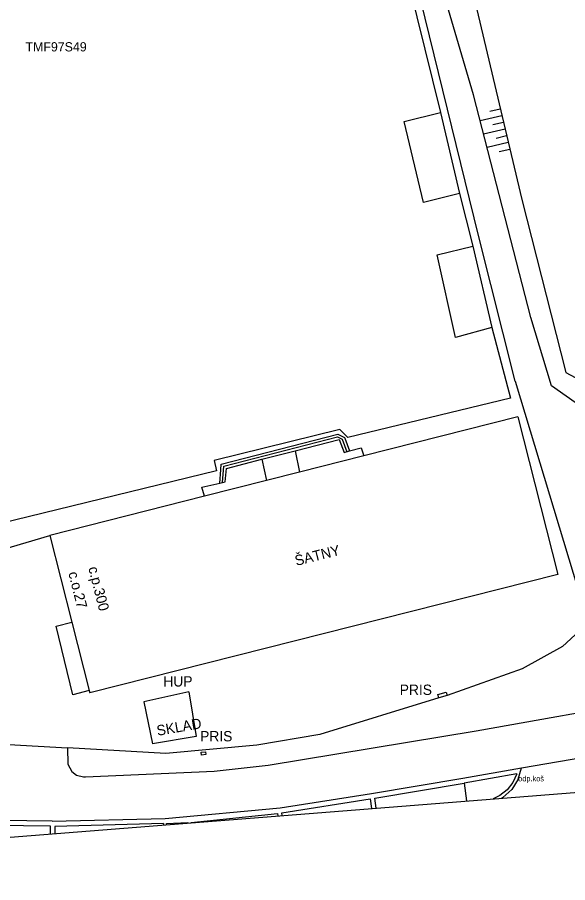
# Model space of a CAD drawing. Extents: x -597791 to -597535, y -1159670 to -1159547.
# Drawn here: x -597726 to -597686, y -1159669.5 to -1159606.7 of the extents above; entities that cross this region are included whole.
import ezdxf

# ---------------------------------------------------------------- set-up
doc = ezdxf.new("R2010")
doc.units = 0
doc.layers.add('MAPA', color=7, linetype='Continuous')
doc.layers.add('Žádosti', color=7, linetype='Continuous')

msp = doc.modelspace()

# ---------------------------------------------------------------- linework, layer by layer
at = {"layer": 'MAPA'}
for p, q in [((-597693.57, -1159662.31), (-597693.402, -1159663.602)), ((-597700.39, -1159663.44), (-597700.291, -1159664.147)), ((-597699.952, -1159664.12), (-597700.04, -1159663.4)), ((-597707.12, -1159664.51), (-597707.098, -1159664.685)), ((-597706.784, -1159664.66), (-597706.81, -1159664.46)), ((-597715.38, -1159665.25), (-597715.377, -1159665.34)), ((-597723.596, -1159665.989), (-597723.6, -1159665.43)), ((-597723.27, -1159665.45), (-597723.28, -1159665.964))]:
    msp.add_line(p, q, dxfattribs=at)
for points in [[(-597714.535, -1159550.725), (-597713.521, -1159552.063), (-597712.34, -1159553.62), (-597701.97, -1159569.58), (-597698.45, -1159581.43), (-597695.48, -1159594.37), (-597692.77, -1159605.67), (-597689.38, -1159619.96), (-597686.19, -1159632.52), (-597681.76, -1159634.88), (-597680.28, -1159632.32), (-597675.87, -1159632.46)], [(-597689.86, -1159633.14), (-597692.53, -1159622.57), (-597699.3, -1159594.96), (-597705.52, -1159569.32)], [(-597698.13, -1159602.09), (-597695.28, -1159613.64)], [(-597688.72, -1159628.53), (-597692.88, -1159612.36), (-597694.69, -1159606.19)], [(-597693.89, -1159619.52), (-597696.52, -1159620.18), (-597697.91, -1159614.3), (-597695.28, -1159613.64)], [(-597695.28, -1159613.64), (-597693.89, -1159619.52)], [(-597692.4, -1159614.24), (-597690.82, -1159613.86)], [(-597691.7, -1159613.56), (-597690.94, -1159613.38)], [(-597691.47, -1159614.53), (-597690.71, -1159614.35)], [(-597692.15, -1159615.2), (-597690.59, -1159614.84)], [(-597691.24, -1159615.5), (-597690.48, -1159615.32)], [(-597691.9, -1159616.17), (-597690.36, -1159615.81)], [(-597691.01, -1159616.48), (-597690.25, -1159616.3)], [(-597693.89, -1159619.52), (-597692.94, -1159623.34)], [(-597691.55, -1159629.25), (-597694.19, -1159629.97), (-597695.52, -1159623.97), (-597692.94, -1159623.34)], [(-597692.94, -1159623.34), (-597691.55, -1159629.25)], [(-597687.23, -1159633.48), (-597688.72, -1159628.53)], [(-597691.55, -1159629.25), (-597690.2, -1159634.37)], [(-597690.2, -1159634.37), (-597702, -1159637.24), (-597702.58, -1159636.66), (-597711.7, -1159638.91), (-597711.53, -1159639.64), (-597724.12, -1159642.71), (-597737.44, -1159645.96), (-597740.78, -1159632.5), (-597753.96, -1159635.73), (-597758.88, -1159636.94)], [(-597675.87, -1159632.46), (-597679.29, -1159633.21), (-597680.19, -1159635.65), (-597682.97, -1159636.48), (-597687.23, -1159633.48)], [(-597689.86, -1159633.14), (-597684.56, -1159650.67)], [(-597689.66, -1159635.74), (-597700.85, -1159638.57)], [(-597689.66, -1159635.74), (-597686.76, -1159647.16)], [(-597711.31, -1159640.54), (-597711.233, -1159639.569), (-597711.2, -1159639.16), (-597702.74, -1159636.98), (-597702.26, -1159637.22), (-597702.234, -1159637.288), (-597701.88, -1159638.21)], [(-597711.1, -1159640.49), (-597711.01, -1159639.31), (-597702.76, -1159637.19), (-597702.42, -1159637.36), (-597702.07, -1159638.26)], [(-597705.82, -1159638.19), (-597702.64, -1159637.37), (-597702.27, -1159638.31), (-597701.88, -1159638.21)], [(-597708.24, -1159638.81), (-597705.82, -1159638.19)], [(-597705.82, -1159638.19), (-597705.51, -1159639.75)], [(-597701.88, -1159638.21), (-597701.03, -1159637.99), (-597700.85, -1159638.57)], [(-597711.31, -1159640.54), (-597710.9, -1159640.45), (-597710.82, -1159639.47), (-597708.24, -1159638.81)], [(-597708.24, -1159638.81), (-597707.9, -1159640.35)], [(-597700.85, -1159638.57), (-597705.51, -1159639.75)], [(-597705.51, -1159639.75), (-597707.9, -1159640.35)], [(-597712.41, -1159641.49), (-597712.6, -1159640.84), (-597711.31, -1159640.54)], [(-597707.9, -1159640.35), (-597712.41, -1159641.49)], [(-597712.41, -1159641.49), (-597723.64, -1159644.34)], [(-597726.62, -1159659.5), (-597727.5, -1159658.36), (-597731.47, -1159657.68), (-597731.64, -1159654.22), (-597727, -1159653.26), (-597728.16, -1159645.66), (-597723.64, -1159644.34)], [(-597723.64, -1159644.34), (-597722.05, -1159650.62)], [(-597686.76, -1159647.16), (-597720.74, -1159655.77)], [(-597720.79, -1159655.6), (-597721.98, -1159655.9), (-597723.18, -1159650.91), (-597722.05, -1159650.62)], [(-597722.05, -1159650.62), (-597720.79, -1159655.6)], [(-597684.56, -1159650.67), (-597686.43, -1159652.4), (-597689.36, -1159654.01), (-597694.8, -1159655.94), (-597695.4, -1159656.12), (-597704.03, -1159658.79), (-597708.62, -1159659.55)], [(-597720.79, -1159655.6), (-597720.74, -1159655.77)], [(-597713.56, -1159655.68), (-597716.82, -1159656.4)], [(-597713.56, -1159655.68), (-597713.01, -1159658.92)], [(-597695.4, -1159656.12), (-597695.47, -1159655.89), (-597694.88, -1159655.7), (-597694.8, -1159655.94)], [(-597722.35, -1159659.75), (-597722.33, -1159660.94), (-597722.05, -1159661.47), (-597721.7, -1159661.74), (-597721.2, -1159661.86), (-597721.06, -1159661.85), (-597711.7, -1159661.44), (-597707.78, -1159661), (-597692.68, -1159658.51), (-597679.89, -1159656.23)], [(-597716.82, -1159656.4), (-597716.19, -1159659.47)], [(-597713.01, -1159658.92), (-597716.19, -1159659.47)], [(-597726.62, -1159659.5), (-597722.35, -1159659.75)], [(-597708.62, -1159659.55), (-597715.23, -1159660.16), (-597722.35, -1159659.75)], [(-597689.39, -1159661.19), (-597679.5, -1159659.5)], [(-597712.65, -1159660.06), (-597712.33, -1159660.03), (-597712.31, -1159660.24), (-597712.63, -1159660.28), (-597712.65, -1159660.06)], [(-597715.26, -1159664.88), (-597706.91, -1159664.11), (-597700.3, -1159663.07), (-597693.65, -1159661.94), (-597689.39, -1159661.19)], [(-597689.64, -1159662.03), (-597689.39, -1159661.19)], [(-597689.73, -1159661.64), (-597693.57, -1159662.31)], [(-597689.73, -1159661.64), (-597690.02, -1159662.26), (-597690.44, -1159662.79), (-597690.98, -1159663.22), (-597691.461, -1159663.449)], [(-597689.64, -1159662.03), (-597690.1, -1159662.77), (-597690.75, -1159663.35), (-597690.854, -1159663.401)], [(-597700.04, -1159663.4), (-597693.57, -1159662.31)], [(-597706.81, -1159664.46), (-597700.39, -1159663.44)], [(-597713.379, -1159665.182), (-597713.38, -1159665.16), (-597707.12, -1159664.51)], [(-597723.47, -1159665.08), (-597732.68, -1159664.96), (-597741.39, -1159664.84)], [(-597723.6, -1159665.43), (-597731.44, -1159665.33)], [(-597723.47, -1159665.08), (-597715.26, -1159664.88)], [(-597715.38, -1159665.25), (-597723.27, -1159665.45)], [(-597715.165, -1159665.323), (-597715.17, -1159665.23), (-597713.61, -1159665.17), (-597713.61, -1159665.2)]]:
    msp.add_lwpolyline(points, dxfattribs=at)
at = {"layer": 'Žádosti'}
msp.add_lwpolyline([(-597654.67, -1159660.54), (-597678.483, -1159546.504), (-597791.46, -1159559.733), (-597772.145, -1159668.212), (-597768.441, -1159669.535)], close=True, dxfattribs=at)

# ---------------------------------------------------------------- texts
at = {"layer": 'MAPA'}
for s, rotation, p in [('ŠATNY', 14.09264, (-597705.75, -1159646.55)), ('c.o.27 ', 284.2042, (-597722.306, -1159647.06)), ('c.p.300', 284.2042, (-597720.852, -1159646.692)), ('SKLAD', 9.81259, (-597715.82, -1159658.88))]:
    msp.add_text(s, height=0.75, rotation=rotation, dxfattribs=at).set_placement(p)
for s, height, p in [('HUP', 0.75, (-597715.4, -1159655.3)), ('PRIS', 0.75, (-597698.24, -1159655.91)), ('PRIS', 0.75, (-597712.73, -1159659.28)), ('odp.koš', 0.4, (-597689.64, -1159662.18))]:
    msp.add_text(s, height=height, dxfattribs=at).set_placement(p)
at = {"layer": 'Žádosti'}
msp.add_text('TMF97S49', height=0.6708, dxfattribs=at).set_placement((-597725.403, -1159609.216))

doc.saveas('drawing.dxf')
